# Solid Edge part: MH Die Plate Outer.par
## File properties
Author: davee
Template: MH Die Plate.par
Last saved by: davee
Revision: 25
Application: Solid Edge
Accuracy: 0.990
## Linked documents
MH Die Plate.par
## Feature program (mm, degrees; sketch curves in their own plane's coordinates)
part copy "CopiedPart_1"
sketch for "Hole_1" plane through (0, 100, -18.1) normal (0, 1, 0) x-axis (-1, 0, 0)
  hole centre (0, 4.44) bore radius 3
hole "Hole_1" finite
delete faces "unnamed DeleteFaces 1"
delete holes assoc c "unnamed DeleteHolesAssocC 1"
delete faces "unnamed DeleteFaces 2"
delete faces "unnamed DeleteFaces 3"
sketch for "ExtrudedCutout_1" plane through (0, 0, 0) normal (0, 0, 1) x-axis (0, -1, 0)
extrude "ExtrudedCutout_1" cut finite 4 along -normal
draft "Draft_1"  Angles1 = 15 deg
delete faces "unnamed DeleteFaces 4"
fillet "Round_1" radius 0.5
delete faces "unnamed DeleteFaces 5"
delete faces "unnamed DeleteFaces 6"
delete faces "unnamed DeleteFaces 7"
delete faces "unnamed DeleteFaces 8"
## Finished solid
Body 1: solid body, 196 faces, 423 edges, 223 vertices.
  Faces by surface: plane 74, cylinder 70, torus 20, cone 16, spline 6, swept 6, sphere 4
  Edges by curve: line 222, circle 159, curve on surface 18, spline 14, ellipse 6, intersection 4
Bounding box of the edges (mm; curved faces can reach further): 200.000 x 200.000 x 36.200, from (-100, -100, -36.2) to (100, 100, 0).
Cylindrical faces by radius (mm): R0.5 x2, R0.7575 x4, R0.808 x6, R1.01 x9, R1.5 x4, R1.515 x2, R2.03 x14, R3 x3, R3.03 x3, R3.045 x2, R5 x6, R5.053 x4, R10 x1, R13.5 x4, R15 x1, R16 x4, R25.8825 x1
Conical faces (half-angle, radius in mm at the cone's reference point): 3 deg R1.515 x8, 3 deg R3.8099 x1, 3 deg R3.8205 x1, 15 deg R2 x2, 59 deg R5.053 x4
Toroidal faces (ring radius, tube radius in mm): R0.505 r1.01 x2, R0.7575 r0.7575 x2, R2.02 r1.01 x2, R2.2725 r0.7575 x2, R2.2818 r0.808 x8, R3.0431 r0.808 x1, R3.0538 r0.808 x1, R5.43 r1.01 x1, R5.4406 r1.01 x1
Spherical faces by radius (mm): R2.03 x4
Planar faces by outward normal: +x 11, +y 8, +z 19, -x 10, -y 8, -z 6, oblique 12
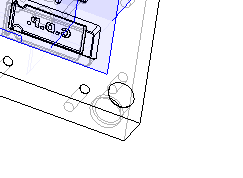
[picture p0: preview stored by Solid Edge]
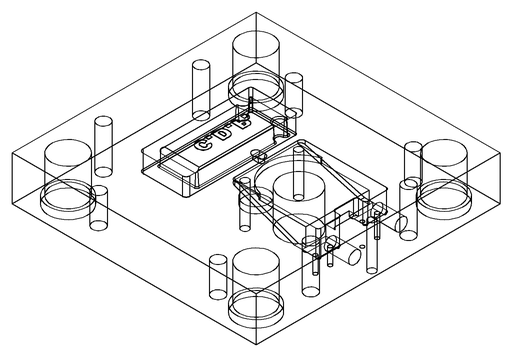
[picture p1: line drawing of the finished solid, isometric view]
